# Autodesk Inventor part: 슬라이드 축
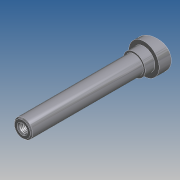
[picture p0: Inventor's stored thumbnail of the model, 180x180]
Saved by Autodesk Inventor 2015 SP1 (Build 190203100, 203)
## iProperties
Created: 2012-05
Part Number: 슬라이드 축
Document SubType Name: 모델링
Designer: SeoGD™
Mass: 21.5729 g
Surface Area: 67.586 cm^2
Volume: 21.5729 cm^3
Density: 1 g/cm^3
Material: 일반
Appearance: 기본값
변환 표준: STEP AP214IS
파일 이름: C:\Users\SeoGD\Desktop\?쒗뿕\異?stp
전처리기: Build: 253, Release: 2010 SP1 - Date: Wed 07/29/2009
전송 단위: 밀리미터
불확실성: 0.01
Author: SeoGD™
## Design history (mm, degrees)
sketch "스케치1"
  geometry: L1 (0, 100)-(7.5, 100); L2 (7.5, 100)-(7.5, 0); L3 (7.5, 0)-(12.5, 0); L4 (12.5, 0)-(12.5, -17); L5 (12.5, -17)-(0, -17); L6 (0, -17)-(0, 100); 1 further point
  constraints: 12 end point, 2 parallel, 2 point on line, 1 perpendicular, 1 vertical
  dimensions: "d0" = 100 distance from line of L1 point (0, 0); "d1" = 15 diameter of L2 L6; "d2" = 25 diameter of L4 L6; "d3" = 17 distance of L3.end L4.end
revolve "회전1" sketch "스케치1" stored, may be unused: angle "d4" = 90 deg
sketch "스케치2"
  geometry: L1 (12.5, 0)-(12.5, -17) reference; L2 (-12.5, -17)-(12.5, -17) reference; L3 (-12.5, 0)-(-12.5, -17) reference; L4 (12.5, -5)-(-12.5, -11.699); L5 (-12.5, 0)-(12.5, 0) reference; 1 further point
  constraints: 2 end point, 2 point on line
  dimensions: "d5" = 75 deg angle of L1 L4; "d6" = 5 distance from line of L4.start L5
extrude "돌출1" cut sketch "스케치2" stored distance "d7" = 10; taper "d8" = 0 deg
chamfer "모따기1" distance "d9" = 1; stored, may be unused: second distance "d10" = 2, angle "d11" = 45 deg
fillet "모깎기1" dims "d12" = 0.5
hole "구멍1" diameter "d15" = 6.647; stored, may be unused: countersink angle "d19" = 90 deg, drill point angle "d21" = 118 deg; dims "d13" = 10, "d14" = 10, "d16" = 17, "d17" = 4, "d18" = 2, "d20" = 20
chamfer "모따기2" distance "d22" = 1; stored, may be unused: second distance "d23" = 2, angle "d24" = 45 deg
sketch "스케치3"
  geometry: C1 r 9 at (0, 0); 1 further point
  constraints: 1 centre point, 1 coincident
  dimensions: "d25" = 18 diameter of C1
extrude "돌출2" join sketch "스케치3" distance "d26" = 8; taper "d27" = 0 deg
node "솔리드1"
node "솔리드 본체"
node "곡면 본체"
node "솔리드2"
